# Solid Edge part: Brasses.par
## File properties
Author: Deepak Maini
Template: normal.par
Last saved by: CADCIM
Revision: 5
Application: Solid Edge
Accuracy: 0.99
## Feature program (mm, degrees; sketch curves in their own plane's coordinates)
sketch for "unnamed RevolvedProtrusion 1" plane through (0, 0, 0) normal (0, -1, 0) x-axis (1, 0, 0)
  line (-32.5, 0) -> (-32.5, 32)
  line (-32.5, 32) -> (-23, 32)
  line (-23, 32) -> (-23, 24)
  line (-23, 24) -> (-14, 24)
  line (-14, 24) -> (-14, 22)
  line (-14, 22) -> (14, 22)
  line (14, 22) -> (14, 24)
  line (14, 24) -> (23, 24)
  line (23, 24) -> (23, 32)
  line (23, 32) -> (32.5, 32)
  line (32.5, 32) -> (32.5, 0)
  line (32.5, 0) -> (-32.5, 0)
revolve "unnamed RevolvedProtrusion 1" add finite 360 deg
sketch for "unnamed Protrusion 1" plane through (0, 0, 0) normal (0, 0, 1) x-axis (1, 0, 0)
  circle centre (0, 0) radius 4
extrude "unnamed Protrusion 1" add finite 30 along -normal
sketch for "Hole_1" plane through (0, 0, -30) normal (0, 0, -1) x-axis (1, 0, 0)
  hole centre (0, 0) bore radius 3
hole "Hole_1" diameter 6 through
sketch for "Hole_2" plane through (32.5, 0, 0) normal (1, 0, 0) x-axis (0, 1, 0)
  hole centre (0, 0) bore radius 16
hole "Hole_2" diameter 32 through
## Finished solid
Body 1: solid body, 16 faces, 18 edges, 0 vertices.
  Faces by surface: cylinder 9, plane 7
  Edges by curve: circle 14, intersection 4
Bounding box of the edges (mm): 65.000 x 64.000 x 64.000, from (-32.5, -32, -32) to (32.5, 32, 32).
Cylindrical faces by radius (mm): R3 x2, R4 x1, R16 x1, R22 x1, R24 x2, R32 x2
Planar faces by outward normal: +x 3, -x 3, -z 1
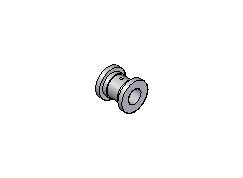
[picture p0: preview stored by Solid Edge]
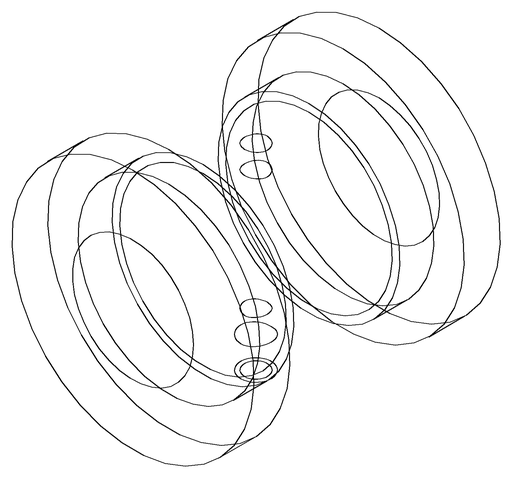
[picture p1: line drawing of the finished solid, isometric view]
